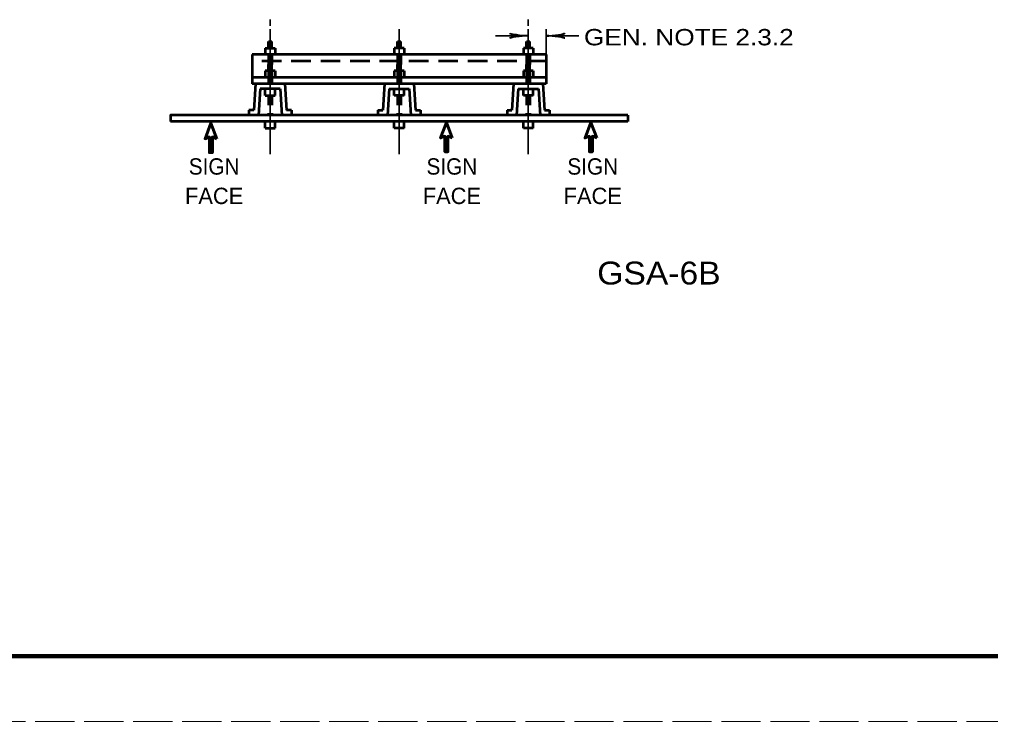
# Model space of a CAD drawing. Extents: x -45 to 635, y -382 to 59.
# Drawn here: x 139.3 to 287.9, y -381.5 to -274.1 of the extents above; entities that cross this region are included whole.
import ezdxf
from ezdxf.enums import TextEntityAlignment as Align

# ---------------------------------------------------------------- set-up
doc = ezdxf.new("R2010")
doc.units = 0
for name, pattern in [('LONG_DASHED', [7.5, 6, -1.5]), ('MEDIUM_DASHED', [4.5, 3, -1.5]), ('SHORT_DASHED', [2.7, 1.5, -1.2])]:
    doc.linetypes.add(name, pattern=pattern)
doc.layers.add('1', color=7, linetype='Continuous', lineweight=53)
doc.layers.add('61', color=7, linetype='Continuous', lineweight=35)

msp = doc.modelspace()

# ---------------------------------------------------------------- linework, layer by layer
at = {"layer": '1', "lineweight": 35}
for p, q in [((177.617, -274.11), (177.617, -275.11)), ((217.117, -274.11), (217.117, -275.11)), ((177.617, -275.61), (177.617, -278.485)), ((197.367, -275.61), (197.367, -278.485)), ((217.117, -275.61), (217.117, -278.485)), ((219.857, -279.485), (219.857, -275.61)), ((212.117, -276.61), (217.117, -276.61)), ((219.857, -276.61), (224.857, -276.61)), ((177.617, -278.485), (177.617, -294.735)), ((197.367, -278.485), (197.367, -294.735)), ((217.117, -278.485), (217.117, -294.735))]:
    msp.add_line(p, q, dxfattribs=at)
at = {"layer": '1'}
for p, q in [((177.367, -277.485), (177.867, -277.485)), ((177.367, -278.485), (177.367, -277.485)), ((177.867, -278.485), (177.867, -277.485)), ((197.117, -277.485), (197.617, -277.485)), ((197.117, -278.485), (197.117, -277.485)), ((197.617, -278.485), (197.617, -277.485)), ((216.867, -277.485), (217.367, -277.485)), ((216.867, -278.485), (216.867, -277.485)), ((217.367, -278.485), (217.367, -277.485)), ((176.867, -278.485), (178.367, -278.485)), ((176.867, -278.485), (176.867, -279.485)), ((178.367, -278.485), (178.367, -279.485)), ((198.117, -278.485), (196.617, -278.485)), ((196.617, -278.485), (196.617, -279.485)), ((198.117, -278.485), (198.117, -279.485)), ((217.867, -278.485), (216.367, -278.485)), ((216.367, -278.485), (216.367, -279.485)), ((217.867, -278.485), (217.867, -279.485)), ((219.857, -279.485), (174.877, -279.485)), ((174.877, -279.485), (174.877, -283.985)), ((219.857, -279.485), (219.857, -283.985)), ((176.867, -281.985), (176.867, -282.985)), ((178.367, -281.985), (176.867, -281.985)), ((177.367, -280.985), (177.867, -280.985)), ((177.367, -281.985), (177.367, -280.985)), ((177.867, -281.985), (177.867, -280.985)), ((178.367, -281.985), (178.367, -282.985)), ((196.617, -281.985), (196.617, -282.985)), ((198.117, -281.985), (196.617, -281.985)), ((197.117, -280.985), (197.617, -280.985)), ((197.117, -281.985), (197.117, -280.985)), ((197.617, -281.985), (197.617, -280.985)), ((198.117, -281.985), (198.117, -282.985)), ((216.367, -281.985), (216.367, -282.985)), ((217.867, -281.985), (216.367, -281.985)), ((216.867, -280.985), (217.367, -280.985)), ((216.867, -281.985), (216.867, -280.985)), ((217.367, -281.985), (217.367, -280.985)), ((217.867, -281.985), (217.867, -282.985)), ((219.857, -282.985), (174.877, -282.985)), ((219.857, -283.985), (174.877, -283.985)), ((175.367, -283.985), (175.117, -287.985)), ((176.072, -284.735), (175.822, -288.735)), ((179.162, -284.735), (176.072, -284.735)), ((176.867, -285.735), (176.867, -284.735)), ((178.367, -285.735), (178.367, -284.735)), ((179.162, -284.735), (179.412, -288.735)), ((179.867, -283.985), (180.117, -287.985)), ((195.117, -283.985), (194.867, -287.985)), ((195.822, -284.735), (195.572, -288.735)), ((195.822, -284.735), (198.912, -284.735)), ((196.617, -285.735), (196.617, -284.735)), ((198.117, -285.735), (198.117, -284.735)), ((198.912, -284.735), (199.163, -288.735)), ((199.617, -283.985), (199.867, -287.985)), ((214.867, -283.985), (214.617, -287.985)), ((215.572, -284.735), (215.322, -288.735)), ((215.572, -284.735), (218.662, -284.735)), ((216.367, -285.735), (216.367, -284.735)), ((217.867, -285.735), (217.867, -284.735)), ((218.662, -284.735), (218.913, -288.735)), ((219.367, -283.985), (219.617, -287.985)), ((176.867, -285.735), (178.367, -285.735)), ((198.117, -285.735), (196.617, -285.735)), ((217.867, -285.735), (216.367, -285.735)), ((175.117, -287.985), (174.367, -287.985)), ((174.367, -287.985), (174.367, -288.735)), ((180.867, -287.985), (180.117, -287.985)), ((180.867, -287.985), (180.867, -288.735)), ((194.117, -287.985), (194.867, -287.985)), ((194.117, -287.985), (194.117, -288.735)), ((199.867, -287.985), (200.617, -287.985)), ((200.617, -287.985), (200.617, -288.735)), ((213.867, -287.985), (214.617, -287.985)), ((213.867, -287.985), (213.867, -288.735)), ((219.617, -287.985), (220.367, -287.985)), ((220.367, -287.985), (220.367, -288.735)), ((232.367, -289.735), (162.367, -289.735)), ((176.867, -290.735), (176.867, -289.735)), ((178.367, -290.735), (178.367, -289.735)), ((196.617, -290.735), (196.617, -289.735)), ((198.117, -290.735), (198.117, -289.735)), ((216.367, -290.735), (216.367, -289.735)), ((217.867, -290.735), (217.867, -289.735)), ((232.367, -288.735), (232.367, -289.735)), ((176.867, -290.735), (178.367, -290.735)), ((198.117, -290.735), (196.617, -290.735)), ((217.867, -290.735), (216.367, -290.735))]:
    msp.add_line(p, q, dxfattribs=at)
at = {"layer": '1', "linetype": 'MEDIUM_DASHED'}
msp.add_line((219.857, -280.485), (174.877, -280.485), dxfattribs=at)
at = {"layer": '1', "linetype": 'SHORT_DASHED'}
for p, q in [((177.367, -279.485), (177.367, -283.985)), ((177.867, -279.485), (177.867, -283.985)), ((197.117, -279.485), (197.117, -283.985)), ((197.617, -279.485), (197.617, -283.985)), ((216.867, -279.485), (216.867, -283.985)), ((217.367, -279.485), (217.367, -283.985)), ((177.367, -285.735), (177.367, -288.735)), ((177.867, -285.735), (177.867, -288.735)), ((197.117, -285.735), (197.117, -288.735)), ((197.617, -285.735), (197.617, -288.735)), ((216.867, -285.735), (216.867, -288.735)), ((217.367, -285.735), (217.367, -288.735))]:
    msp.add_line(p, q, dxfattribs=at)
at = {"layer": '1'}
msp.add_lwpolyline([(232.367, -288.735), (162.367, -288.735), (162.367, -289.735)], dxfattribs=at)
at = {"layer": '1', "lineweight": 60}
for points in [[(169.463, -292.356), (168.564, -289.971), (167.663, -292.356), (168.338, -292.086), (168.338, -294.471), (168.788, -294.471), (168.788, -292.086)], [(205.49, -292.24), (204.59, -289.855), (203.69, -292.24), (204.365, -291.97), (204.365, -294.355), (204.815, -294.355), (204.815, -291.97)], [(227.601, -292.24), (226.701, -289.855), (225.801, -292.24), (226.476, -291.97), (226.476, -294.355), (226.926, -294.355), (226.926, -291.97)]]:
    msp.add_lwpolyline(points, close=True, dxfattribs=at)
at = {"layer": '1', "lineweight": 40}
for centre, major_axis, ratio, start_param, end_param in [((215.997, -276.399), (1.756, -0.176), 0.07063, 3.1407148, 5.41811), ((220.948, -276.334), (-1.786, -0.156), 0.122415, 0.8963533, 3.1415927), ((220.948, -276.334), (-1.786, -0.156), 0.122415, 0.8963533, 3.1415927), ((216.026, -276.886), (1.786, 0.156), 0.122415, 0.8963533, 3.1415927), ((220.978, -276.822), (-1.756, 0.176), 0.07063, 3.1407148, 5.41811), ((220.978, -276.822), (-1.756, 0.176), 0.07063, 3.1407148, 5.41811)]:
    msp.add_ellipse(centre, major_axis=major_axis, ratio=ratio, start_param=start_param, end_param=end_param, dxfattribs=at)
at = {"layer": '61', "lineweight": 158}
msp.add_line((624.229, -371.5), (-14.831, -371.48), dxfattribs=at)
at = {"layer": '61', "linetype": 'LONG_DASHED', "lineweight": 13}
msp.add_line((635.169, -381.48), (-44.891, -381.5), dxfattribs=at)

# ---------------------------------------------------------------- texts
at = {"layer": '1'}
for s, height, width, p in [('GEN. NOTE 2.3.2', 2.5, 1.2, (241.688, -278.072)), ('SIGN', 2.5, 0.95, (169.054, -297.847)), ('SIGN', 2.5, 0.95, (205.429, -297.847)), ('SIGN', 2.5, 0.95, (226.986, -297.847)), ('GSA-6B', 3.5, 1.1, (237.109, -314.653))]:
    msp.add_text(s, height=height, dxfattribs=dict(at, width=width)).set_placement(p, align=Align.CENTER)
for p in [(169.053, -302.347), (205.429, -302.347), (226.985, -302.347)]:
    msp.add_text('FACE', height=2.5, dxfattribs=at).set_placement(p, align=Align.CENTER)

doc.saveas('drawing.dxf')
